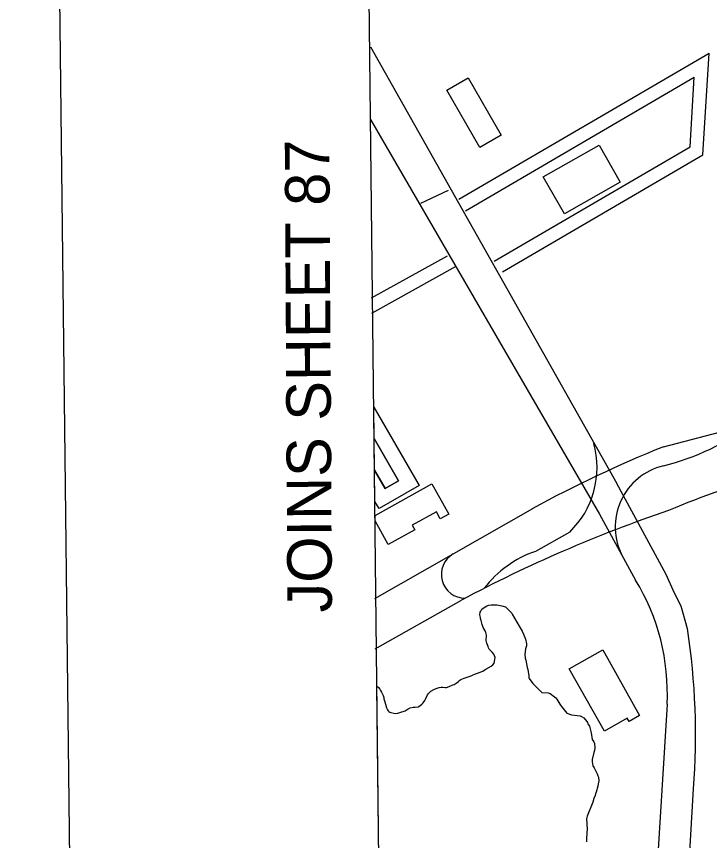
# Model space of a CAD drawing. Extents: x 3683402 to 3721514, y 487807 to 513565.
# Drawn here: x 3686743 to 3688299, y 501740 to 503591 of the extents above; entities that cross this region are included whole.
import ezdxf

# ---------------------------------------------------------------- set-up
doc = ezdxf.new("R2010")
doc.units = 0
for name, color, linetype in [('V-ANNO-SYMB', 7, 'Continuous'), ('V-ANNO-TEXT', 7, 'Continuous'), ('V-BLDG-OTLN', 7, 'Continuous'), ('V-GRID-FRAM', 7, 'Continuous'), ('V-ROAD-CNTR', 7, 'Continuous'), ('V-SITE-VEGE', 7, 'Continuous')]:
    doc.layers.add(name, color=color, linetype=linetype)

msp = doc.modelspace()

# ---------------------------------------------------------------- linework, layer by layer
at = {"layer": 'V-ANNO-SYMB'}
msp.add_lwpolyline([(3687009, 489047.6), (3720089.9, 489432.1), (3719823.5, 512347.2), (3686742.6, 511962.6), (3687009, 489047.6)], dxfattribs=at)
at = {"layer": 'V-BLDG-OTLN'}
for p, q in [((3687546.2, 502643), (3687545.4, 502713.6)), ((3687545.4, 502713.6), (3687646.8, 502537.7)), ((3687600.9, 502547.7), (3687546.2, 502643)), ((3687547, 502572.1), (3687546.2, 502643)), ((3687546.2, 502643), (3687600.9, 502547.7)), ((3687547.7, 502501.9), (3687547, 502572.1)), ((3687547, 502572.1), (3687570.9, 502530.5)), ((3687570.9, 502530.5), (3687547, 502572.1)), ((3687570.9, 502530.5), (3687600.9, 502547.7)), ((3687600.9, 502547.7), (3687570.9, 502530.5)), ((3687548.1, 502470.1), (3687675.8, 502541.1)), ((3687646.8, 502537.7), (3687557, 502485.9)), ((3687675.8, 502541.1), (3687713.6, 502473.1)), ((3687557, 502485.9), (3687547.7, 502501.9)), ((3687685.8, 502478.5), (3687631.6, 502448.4)), ((3687694.7, 502462.5), (3687685.8, 502478.5)), ((3687713.6, 502473.1), (3687694.7, 502462.5)), ((3687548.2, 502458.1), (3687548.1, 502470.1)), ((3687577.8, 502405.1), (3687548.2, 502458.1)), ((3687637.3, 502438.2), (3687577.8, 502405.1)), ((3687631.6, 502448.4), (3687637.3, 502438.2))]:
    msp.add_line(p, q, dxfattribs=at)
for points in [[(3687783.5, 503297.2), (3687709.2, 503426), (3687757.1, 503453.6), (3687831.4, 503324.8)], [(3687926, 503231.2), (3688051.6, 503302.4), (3688098.9, 503218.9), (3687973.4, 503147.7)], [(3688059.7, 502168.1), (3688142.3, 502021), (3688118.6, 502007.7), (3688114.7, 502014.6), (3688063.2, 501985.7), (3687984.5, 502125.9)]]:
    msp.add_lwpolyline(points, close=True, dxfattribs=at)
at = {"layer": 'V-GRID-FRAM'}
msp.add_lwpolyline([(3687448, 511403.5), (3719130.8, 511772.1), (3719350.3, 493590.7), (3687651.7, 493221.8), (3687448, 511403.5)], dxfattribs=at)
at = {"layer": 'V-ROAD-CNTR'}
for points in [[(3687538, 503523.2), (3688091, 502541.7)], [(3687736.1, 503180.7), (3688298.6, 503508.8)], [(3688284.5, 503280.4), (3688298.6, 503508.8)], [(3687751.4, 503154.9), (3688265.2, 503454.6)], [(3688255.6, 503298.2), (3688265.2, 503454.6)], [(3687538, 503359.9), (3688052.4, 502472.8)], [(3687815.6, 503041.6), (3688255.6, 503298.2)], [(3687834, 503017.6), (3688284.5, 503280.4)], [(3687712.4, 503200.2), (3687650.4, 503171.3)], [(3687710.4, 503053), (3687539.6, 502958.1)], [(3687729.8, 503029.4), (3687540, 502924)], [(3688195.8, 502624.3), (3689522.6, 502971.6)], [(3688250.1, 502215.9), (3688235.9, 502266.6), (3688220.5, 502295.5), (3688202.2, 502337.6), (3688091, 502541.7)], [(3687901.4, 502485.2), (3687547.2, 502283.3)], [(3688052.4, 502472.8), (3688133.4, 502325)], [(3687985.4, 502432.9), (3687908.4, 502389.6)], [(3687548.4, 502170.4), (3687742.2, 502279.9)], [(3688204, 502046.4), (3688156.3, 501273.4), (3688097.9, 500198.9), (3688019.9, 498919.8)], [(3688146.9, 499792), (3688144.9, 499885.7), (3688142.8, 500016.6), (3688163.3, 500399.5), (3688229.7, 501274.6), (3688263.3, 501856.3)]]:
    msp.add_lwpolyline(points, dxfattribs=at)
for centre, radius, start, end in [((3688056.5, 503136.4), 571.8, 284.1033, 306.5312), ((3689181.5, 500156.8), 2657.1, 111.7763, 118.8018), ((3687844.4, 502578.1), 202.4, 314.1502, 15.5271), ((3688228.6, 502444.7), 141, 103.4121, 207.926), ((3689182.9, 500130.4), 2545.4, 106.9191, 112.5321), ((3689209, 499530.9), 3115.8, 108.7476, 118.0829), ((3687750.1, 502337.6), 53.2, 119.5114, 270.5624), ((3687987.1, 502159.2), 243.5, 108.8718, 142.7369), ((3687716.2, 502071), 488.5, 357.1128, 31.3298), ((3686679.2, 501978.1), 1588.8, 355.6025, 8.6105)]:
    msp.add_arc(centre, radius, start, end, dxfattribs=at)
at = {"layer": 'V-SITE-VEGE'}
for p, q in [((3687798, 502266.4), (3687804, 502268.5)), ((3687804, 502268.5), (3687808.7, 502269.2)), ((3687808.7, 502269.2), (3687821.7, 502269.1)), ((3687821.7, 502269.1), (3687829, 502268.1)), ((3687783.7, 502246.7), (3687784.5, 502253)), ((3687784.5, 502253), (3687785.4, 502255.6)), ((3687785.4, 502255.6), (3687787.8, 502259.6)), ((3687787.8, 502259.6), (3687798, 502266.4)), ((3687829, 502268.1), (3687833, 502267.4)), ((3687833, 502267.4), (3687841.1, 502264.7)), ((3687841.1, 502264.7), (3687855.4, 502250.4)), ((3687855.4, 502250.4), (3687856.1, 502248.5)), ((3687784.6, 502241), (3687783.7, 502246.7)), ((3687785.3, 502239.1), (3687784.6, 502241)), ((3687786.2, 502234.6), (3687785.3, 502239.1)), ((3687788.5, 502224.9), (3687786.2, 502234.6)), ((3687856.1, 502248.5), (3687871.5, 502221.9)), ((3687790.6, 502218.5), (3687788.5, 502224.9)), ((3687795.8, 502210.9), (3687790.6, 502218.5)), ((3687871.5, 502221.9), (3687874.3, 502217.9)), ((3687874.3, 502217.9), (3687878.5, 502210.5)), ((3687797.2, 502207.6), (3687795.8, 502210.9)), ((3687798.3, 502201.6), (3687797.2, 502207.6)), ((3687797.7, 502189.1), (3687798.3, 502201.6)), ((3687878.5, 502210.5), (3687881.8, 502203.4)), ((3687881.8, 502203.4), (3687885.9, 502192.5)), ((3687798.9, 502183.2), (3687797.7, 502189.1)), ((3687801.9, 502175.6), (3687798.9, 502183.2)), ((3687885.9, 502192.5), (3687888.5, 502181.9)), ((3687888.2, 502177.2), (3687886.2, 502170.3)), ((3687888.5, 502181.9), (3687888.2, 502177.2)), ((3687802.8, 502173), (3687801.9, 502175.6)), ((3687804.7, 502170.2), (3687802.8, 502173)), ((3687811.3, 502163.3), (3687804.7, 502170.2)), ((3687814.8, 502158.8), (3687811.3, 502163.3)), ((3687816.7, 502155), (3687814.8, 502158.8)), ((3687886.2, 502170.3), (3687884.5, 502157.6)), ((3687884.5, 502157.6), (3687885.6, 502149.8)), ((3687815.8, 502138.7), (3687817.6, 502151.4)), ((3687817.6, 502151.4), (3687816.7, 502155)), ((3687885.6, 502149.8), (3687886.8, 502145.3)), ((3687886.8, 502145.3), (3687890, 502128.5)), ((3687778.3, 502115.8), (3687789.9, 502120.6)), ((3687789.9, 502120.6), (3687793.3, 502122.5)), ((3687793.3, 502122.5), (3687797.3, 502124.6)), ((3687797.3, 502124.6), (3687808.9, 502131.6)), ((3687808.9, 502131.6), (3687813, 502134.9)), ((3687813, 502134.9), (3687815.8, 502138.7)), ((3687890, 502128.5), (3687890.7, 502126.1)), ((3687890.7, 502126.1), (3687891.1, 502124)), ((3687891.1, 502124), (3687893.4, 502110)), ((3687740.7, 502101.4), (3687748.2, 502104.9)), ((3687748.2, 502104.9), (3687762, 502109.5)), ((3687762, 502109.5), (3687767, 502111.3)), ((3687767, 502111.3), (3687773.8, 502114.1)), ((3687773.8, 502114.1), (3687778.3, 502115.8)), ((3687893.4, 502110), (3687893.8, 502106.4)), ((3687893.8, 502106.4), (3687894.5, 502103.6)), ((3687894.5, 502103.6), (3687902.3, 502092.4)), ((3687558.2, 501567.5), (3687552.4, 502086.4)), ((3687552.4, 502086.4), (3687554.1, 502085.2)), ((3687554.1, 502085.2), (3687555.7, 502083.5)), ((3687555.7, 502083.5), (3687558.8, 502079.9)), ((3687685, 502081.4), (3687692.3, 502083.5)), ((3687692.3, 502083.5), (3687696.8, 502084.4)), ((3687696.8, 502084.4), (3687700.6, 502084.4)), ((3687700.6, 502084.4), (3687705.8, 502084.1)), ((3687705.8, 502084.1), (3687708.4, 502084.1)), ((3687708.4, 502084.1), (3687711, 502084.8)), ((3687711, 502084.8), (3687716.4, 502086.6)), ((3687716.4, 502086.6), (3687722.8, 502089.7)), ((3687722.8, 502089.7), (3687725.7, 502090.8)), ((3687725.7, 502090.8), (3687730.2, 502093.6)), ((3687730.2, 502093.6), (3687735.2, 502097.1)), ((3687735.2, 502097.1), (3687736.6, 502098.8)), ((3687736.6, 502098.8), (3687740.7, 502101.4)), ((3687902.3, 502092.4), (3687904.1, 502091)), ((3687904.1, 502091), (3687907, 502088.6)), ((3687907, 502088.6), (3687917.3, 502077.5)), ((3687558.8, 502079.9), (3687560.6, 502076.9)), ((3687560.6, 502076.9), (3687562.5, 502073.5)), ((3687562.5, 502073.5), (3687563.4, 502071.6)), ((3687563.4, 502071.6), (3687566, 502065.7)), ((3687566, 502065.7), (3687566.9, 502063.3)), ((3687661.6, 502057.2), (3687666, 502067.6)), ((3687666, 502067.6), (3687667.9, 502070)), ((3687667.9, 502070), (3687673.6, 502075.6)), ((3687673.6, 502075.6), (3687680, 502079.3)), ((3687680, 502079.3), (3687685, 502081.4)), ((3687917.3, 502077.5), (3687922.4, 502072.5)), ((3687922.4, 502072.5), (3687937.1, 502071.4)), ((3687937.1, 502071.4), (3687941.8, 502070.4)), ((3687941.8, 502070.4), (3687951.4, 502063)), ((3687566.9, 502063.3), (3687567.6, 502061)), ((3687567.6, 502061), (3687568.1, 502058.1)), ((3687568.1, 502058.1), (3687568.8, 502056.2)), ((3687568.8, 502056.2), (3687569.7, 502051.7)), ((3687569.7, 502051.7), (3687571.5, 502046.5)), ((3687571.5, 502046.5), (3687573.8, 502038.2)), ((3687648.8, 502042.4), (3687653.3, 502046.4)), ((3687653.3, 502046.4), (3687656.2, 502049.5)), ((3687656.2, 502049.5), (3687660, 502054.2)), ((3687660, 502054.2), (3687661.6, 502057.2)), ((3687951.4, 502063), (3687954.3, 502060.4)), ((3687954.3, 502060.4), (3687956.4, 502057.3)), ((3687956.4, 502057.3), (3687963.1, 502046.2)), ((3687573.8, 502038.2), (3687575.7, 502033.7)), ((3687575.7, 502033.7), (3687577.3, 502031.1)), ((3687577.3, 502031.1), (3687579.2, 502029.5)), ((3687579.2, 502029.5), (3687581.1, 502028.3)), ((3687581.1, 502028.3), (3687583.2, 502027.3)), ((3687599.5, 502026.2), (3687603.5, 502027.9)), ((3687603.5, 502027.9), (3687615.6, 502031.6)), ((3687615.6, 502031.6), (3687622.5, 502035.8)), ((3687622.5, 502035.8), (3687624.2, 502036.9)), ((3687624.2, 502036.9), (3687626.8, 502038.3)), ((3687626.8, 502038.3), (3687633.4, 502039.2)), ((3687633.4, 502039.2), (3687638.1, 502039.2)), ((3687638.1, 502039.2), (3687644.7, 502040.3)), ((3687644.7, 502040.3), (3687648.8, 502042.4)), ((3687963.1, 502046.2), (3687964.5, 502044)), ((3687964.5, 502044), (3687967.1, 502040.9)), ((3687967.1, 502040.9), (3687978.6, 502026)), ((3687583.2, 502027.3), (3687590, 502025.8)), ((3687590, 502025.8), (3687595, 502025.3)), ((3687595, 502025.3), (3687599.5, 502026.2)), ((3687978.6, 502026), (3687989.5, 502022.1)), ((3687989.5, 502022.1), (3688008.6, 502019.9)), ((3688008.6, 502019.9), (3688012.1, 502018.9)), ((3688012.1, 502018.9), (3688016.8, 502015.8)), ((3688016.8, 502015.8), (3688024.1, 502007.7)), ((3688024.1, 502007.7), (3688025.5, 502004.9)), ((3688025.5, 502004.9), (3688026.4, 502002.2)), ((3688026.4, 502002.2), (3688029.7, 501996.8)), ((3688029.7, 501996.8), (3688033.4, 501981.9)), ((3688033.4, 501981.9), (3688034.3, 501976.7)), ((3688034.3, 501976.7), (3688035, 501971.9)), ((3688035, 501971.9), (3688036.1, 501967)), ((3688036.1, 501967), (3688039.6, 501961.5)), ((3688039.6, 501961.5), (3688040.8, 501958.2)), ((3688040.8, 501958.2), (3688041.6, 501948.5)), ((3688039.9, 501937.9), (3688035.8, 501921.8)), ((3688040.9, 501942.3), (3688039.9, 501937.9)), ((3688041.6, 501948.5), (3688040.9, 501942.3)), ((3688035.8, 501921.8), (3688035.5, 501916.6)), ((3688035.5, 501916.6), (3688037.3, 501908.1)), ((3688037.3, 501908.1), (3688040.1, 501903.1)), ((3688040.1, 501903.1), (3688046.9, 501889.8)), ((3688046.9, 501889.8), (3688048.5, 501885.3)), ((3688048.5, 501885.3), (3688049.7, 501882.5)), ((3688049.7, 501882.5), (3688050.8, 501873.7)), ((3688048.6, 501862.4), (3688045, 501848.3)), ((3688049.6, 501867.1), (3688048.6, 501862.4)), ((3688050.8, 501873.7), (3688049.6, 501867.1)), ((3688043.5, 501844.5), (3688042.6, 501841.2)), ((3688045, 501848.3), (3688043.5, 501844.5)), ((3688037.2, 501825.9), (3688024.5, 501794.7)), ((3688039.9, 501834.6), (3688037.2, 501825.9)), ((3688042.6, 501841.2), (3688039.9, 501834.6)), ((3688024.5, 501794.7), (3688023.3, 501788.6)), ((3688023.3, 501788.6), (3688023.7, 501777.7)), ((3688023.7, 501777.7), (3688024.1, 501774.9)), ((3688024.1, 501774.9), (3688024.8, 501766.6)), ((3688024.8, 501766.6), (3688023, 501744.4)), ((3688023, 501744.4), (3688023.2, 501737.3))]:
    msp.add_line(p, q, dxfattribs=at)

# ---------------------------------------------------------------- texts
at = {"layer": 'V-ANNO-TEXT'}
msp.add_text('JOINS SHEET 87', height=100, rotation=90.325, dxfattribs=at).set_placement((3687451.3, 502252.4))

doc.saveas('drawing.dxf')
